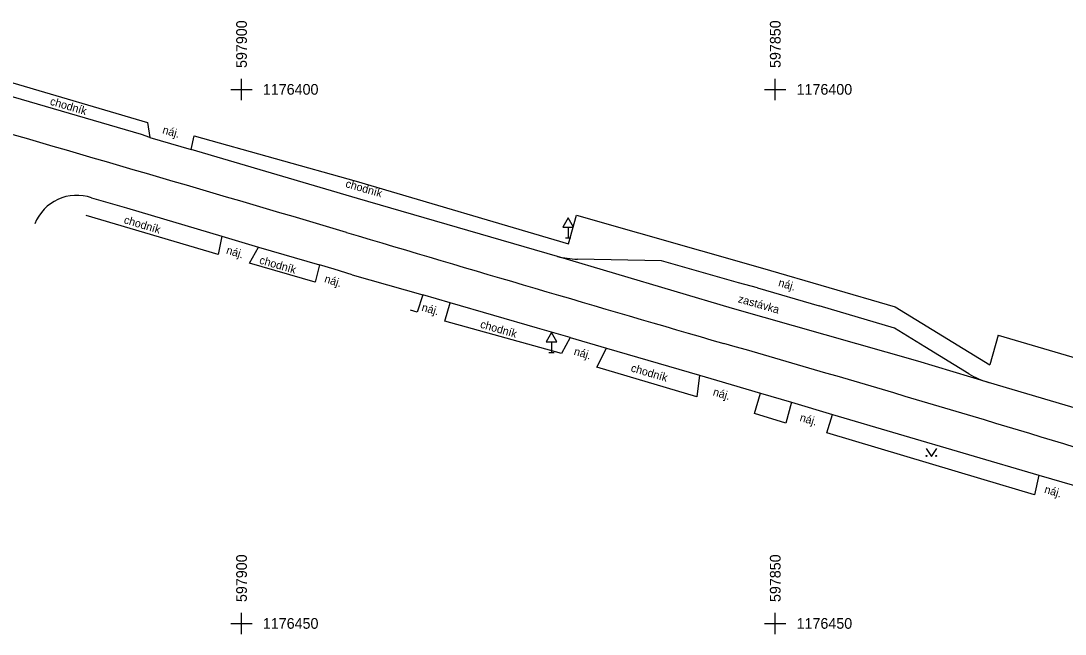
# Model space of a CAD drawing. Extents: x -598160 to -596067, y -1177005 to -1176344.
# Drawn here: x -597920.7 to -597822.8, y -1176451 to -1176393.6 of the extents above; entities that cross this region are included whole.
import ezdxf

# ---------------------------------------------------------------- set-up
doc = ezdxf.new("R2010")
doc.units = 0
for name, color, linetype in [('bez obruby', 7, 'Continuous'), ('dopravní značení svislé', 7, 'Continuous'), ('hektametrová síť', 7, 'Continuous'), ('obruba +0 cm', 7, 'Continuous'), ('obruba +12 cm', 7, 'Continuous'), ('obruba +3 cm', 7, 'Continuous'), ('popis ploch', 7, 'Continuous'), ('rozhraní ploch', 7, 'Continuous'), ('vodorovné značení', 7, 'Continuous'), ('zeleň', 7, 'Continuous')]:
    doc.layers.add(name, color=color, linetype=linetype)

msp = doc.modelspace()

# ---------------------------------------------------------------- linework, layer by layer
at = {"layer": 'bez obruby'}
for p, q in [((-597854.01, -1176420.52), (-597870.41, -1176415.65)), ((-597836.65, -1176425.44), (-597854.01, -1176420.52)), ((-597830.01, -1176427.44), (-597836.65, -1176425.44))]:
    msp.add_line(p, q, dxfattribs=at)
at = {"layer": 'dopravní značení svislé'}
for p, q in [((-597869.4, -1176412.892), (-597869.4, -1176413.91)), ((-597869.65, -1176413.91), (-597869.15, -1176413.91)), ((-597870.97, -1176423.632), (-597870.97, -1176424.65)), ((-597871.22, -1176424.65), (-597870.72, -1176424.65))]:
    msp.add_line(p, q, dxfattribs=at)
for points in [[(-597869.9, -1176412.892), (-597868.9, -1176412.892), (-597869.4, -1176412.026)], [(-597871.47, -1176423.632), (-597870.47, -1176423.632), (-597870.97, -1176422.766)]]:
    msp.add_lwpolyline(points, close=True, dxfattribs=at)
at = {"layer": 'hektametrová síť'}
for p, q in [((-597900, -1176401), (-597900, -1176399)), ((-597850, -1176401), (-597850, -1176399)), ((-597901, -1176400), (-597899, -1176400)), ((-597851, -1176400), (-597849, -1176400)), ((-597900, -1176451), (-597900, -1176449)), ((-597850, -1176451), (-597850, -1176449)), ((-597901, -1176450), (-597899, -1176450)), ((-597851, -1176450), (-597849, -1176450))]:
    msp.add_line(p, q, dxfattribs=at)
at = {"layer": 'obruba +0 cm'}
for p, q in [((-597901.83, -1176413.75), (-597898.41, -1176414.78)), ((-597891.31, -1176416.83), (-597892.69, -1176416.43)), ((-597889.65, -1176417.35), (-597891.31, -1176416.83)), ((-597880.455, -1176419.993), (-597883.03, -1176419.25)), ((-597869.2, -1176423.24), (-597865.82, -1176424.24)), ((-597857.1, -1176426.77), (-597855.5, -1176427.24)), ((-597855.5, -1176427.24), (-597851.38, -1176428.44)), ((-597820.21, -1176430.35), (-597830.01, -1176427.44)), ((-597848.48, -1176429.3), (-597844.63, -1176430.45)), ((-597825.3, -1176436.12), (-597821.97, -1176437.1))]:
    msp.add_line(p, q, dxfattribs=at)
at = {"layer": 'obruba +12 cm'}
for p, q in [((-597909.36, -1176404.24), (-597924.07, -1176399.95)), ((-597908.59, -1176404.5), (-597909.36, -1176404.24)), ((-597889.14, -1176410.21), (-597904.72, -1176405.63)), ((-597914.04, -1176410.15), (-597910.77, -1176411.1)), ((-597870.41, -1176415.65), (-597889.14, -1176410.21)), ((-597910.77, -1176411.1), (-597901.83, -1176413.75)), ((-597898.41, -1176414.78), (-597892.69, -1176416.43)), ((-597860.67, -1176416.06), (-597868.54, -1176415.9)), ((-597853.45, -1176418.11), (-597860.67, -1176416.06)), ((-597889.65, -1176417.35), (-597883.03, -1176419.25)), ((-597851.66, -1176418.57), (-597853.45, -1176418.11)), ((-597872.28, -1176422.35), (-597880.455, -1176419.993)), ((-597838.84, -1176422.35), (-597845.9, -1176420.28)), ((-597869.2, -1176423.24), (-597872.28, -1176422.35)), ((-597835.98, -1176424.1), (-597838.84, -1176422.35)), ((-597865.82, -1176424.24), (-597857.1, -1176426.77)), ((-597831.88, -1176426.63), (-597835.98, -1176424.1)), ((-597851.38, -1176428.44), (-597848.48, -1176429.3)), ((-597844.63, -1176430.45), (-597838.47, -1176432.24)), ((-597838.47, -1176432.24), (-597825.3, -1176436.12))]:
    msp.add_line(p, q, dxfattribs=at)
for centre, radius, start, end in [((-597868.006, -1176404.785), 11.127, 257.52223, 267.24834), ((-597827.611, -1176419.338), 8.45, 239.65412, 253.5057)]:
    msp.add_arc(centre, radius, start, end, dxfattribs=at)
at = {"layer": 'obruba +3 cm'}
for p, q in [((-597908.59, -1176404.5), (-597904.72, -1176405.63)), ((-597851.66, -1176418.57), (-597845.9, -1176420.28))]:
    msp.add_line(p, q, dxfattribs=at)
msp.add_arc((-597915.421, -1176414.168), 4.248, 71.02568, 158.34723, dxfattribs=at)
at = {"layer": 'rozhraní ploch'}
for p, q in [((-597921.97, -1176399.22), (-597908.81, -1176403.11)), ((-597908.81, -1176403.11), (-597908.59, -1176404.5)), ((-597904.72, -1176405.63), (-597904.45, -1176404.34)), ((-597904.45, -1176404.34), (-597889.27, -1176408.6)), ((-597889.27, -1176408.6), (-597869.36, -1176414.45)), ((-597902.18, -1176415.45), (-597914.55, -1176411.82)), ((-597869.36, -1176414.45), (-597868.62, -1176411.77)), ((-597868.62, -1176411.77), (-597851.2, -1176416.75)), ((-597901.83, -1176413.75), (-597902.18, -1176415.45)), ((-597899.26, -1176416.27), (-597898.41, -1176414.78)), ((-597893.11, -1176418.04), (-597899.26, -1176416.27)), ((-597892.69, -1176416.43), (-597893.11, -1176418.04)), ((-597851.2, -1176416.75), (-597838.76, -1176420.35)), ((-597883.03, -1176419.25), (-597883.56, -1176420.85)), ((-597883.56, -1176420.85), (-597884.17, -1176420.67)), ((-597880.95, -1176421.71), (-597880.455, -1176419.993)), ((-597838.76, -1176420.35), (-597829.91, -1176425.79)), ((-597870.02, -1176424.73), (-597880.95, -1176421.71)), ((-597869.2, -1176423.24), (-597870.02, -1176424.73)), ((-597829.12, -1176423), (-597829.91, -1176425.79)), ((-597829.12, -1176423), (-597803.47, -1176430.57)), ((-597866.73, -1176426.02), (-597865.82, -1176424.24)), ((-597857.36, -1176428.79), (-597866.73, -1176426.02)), ((-597857.1, -1176426.77), (-597857.36, -1176428.79)), ((-597851.95, -1176430.34), (-597851.38, -1176428.44)), ((-597848.48, -1176429.3), (-597849.01, -1176431.24)), ((-597849.01, -1176431.24), (-597851.95, -1176430.34)), ((-597845.17, -1176432.15), (-597844.63, -1176430.45)), ((-597830.74, -1176436.45), (-597845.17, -1176432.15)), ((-597825.3, -1176436.12), (-597825.72, -1176437.97)), ((-597825.72, -1176437.97), (-597830.74, -1176436.45))]:
    msp.add_line(p, q, dxfattribs=at)
at = {"layer": 'vodorovné značení'}
for centre, radius, start, end in [((-599574.267, -1182105.767), 5936.273, 73.5190771, 73.920875), ((-596380.976, -1171350.275), 5283.256, 253.401929, 253.801436), ((-598414.666, -1178378.527), 2033.326, 73.020065, 74.018309)]:
    msp.add_arc(centre, radius, start, end, dxfattribs=at)
at = {"layer": 'zeleň'}
msp.add_lwpolyline([(-597835.876, -1176433.614), (-597835.376, -1176434.364), (-597834.876, -1176433.614)], dxfattribs=at)
for centre in [(-597835.826, -1176434.314), (-597834.927, -1176434.314)]:
    msp.add_circle(centre, 0.05, dxfattribs=at)

# ---------------------------------------------------------------- texts
at = {"layer": 'hektametrová síť'}
for s, p in [('597900', (-597899.5, -1176398)), ('597850', (-597849.5, -1176398)), ('597900', (-597899.5, -1176448)), ('597850', (-597849.5, -1176448))]:
    msp.add_text(s, height=1, rotation=90, dxfattribs=at).set_placement(p)
for s, p in [('1176400', (-597898, -1176400.5)), ('1176400', (-597848, -1176400.5)), ('1176450', (-597898, -1176450.5)), ('1176450', (-597848, -1176450.5))]:
    msp.add_text(s, height=1, dxfattribs=at).set_placement(p)
at = {"layer": 'popis ploch'}
for s, rotation, p in [('chodník', 343.74129, (-597918, -1176401.427)), ('náj.', 343.72274, (-597907.463, -1176404.1)), ('chodník', 343.80442, (-597890.317, -1176409.139)), ('chodník', 343.48909, (-597911.081, -1176412.52)), ('náj.', 343.2393, (-597901.489, -1176415.367)), ('chodník', 343.90918, (-597898.39, -1176416.295)), ('náj.', 342.60668, (-597892.296, -1176418.041)), ('náj.', 343.46516, (-597849.767, -1176418.402)), ('zastávka', 344.17673, (-597853.545, -1176419.924)), ('náj.', 343.91391, (-597883.181, -1176420.715)), ('chodník', 343.91391, (-597877.698, -1176422.297)), ('náj.', 343.51873, (-597868.921, -1176424.835)), ('chodník', 343.82057, (-597863.584, -1176426.398)), ('náj.', 343.76116, (-597855.892, -1176428.636)), ('náj.', 343.36905, (-597847.756, -1176431.03)), ('náj.', 343.60114, (-597824.848, -1176437.765))]:
    msp.add_text(s, height=0.75, rotation=rotation, dxfattribs=at).set_placement(p)

doc.saveas('drawing.dxf')
